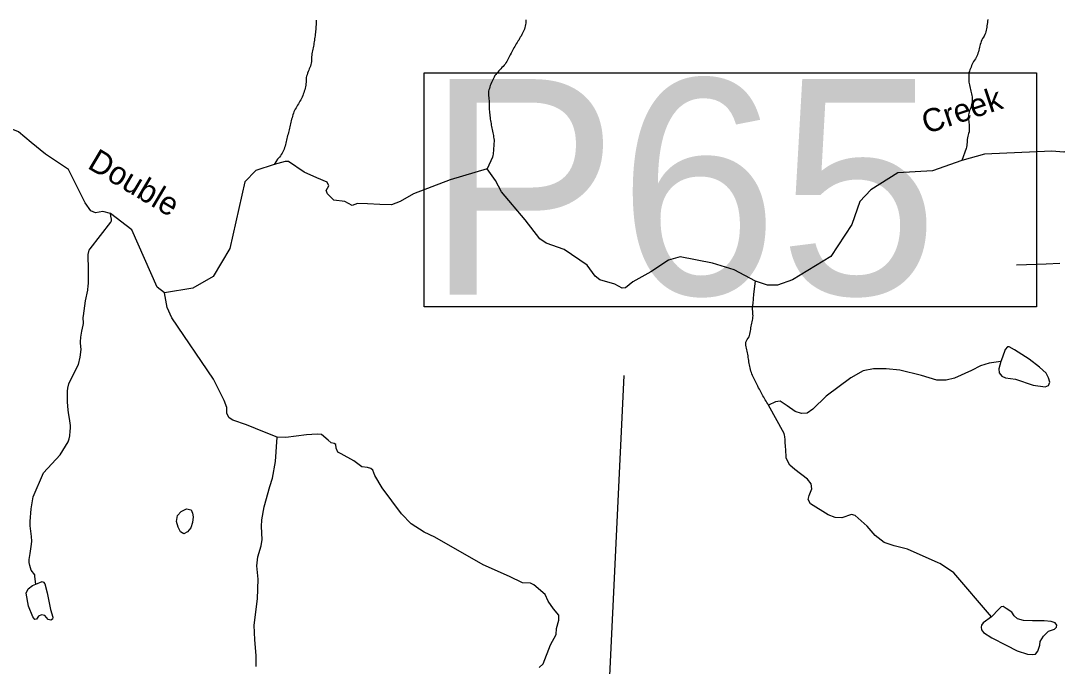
# Model space of a CAD drawing. Extents: x 1950930 to 2061844, y 904556 to 1017002.
# Drawn here: x 1972240 to 1978977, y 947382 to 951576 of the extents above; entities that cross this region are included whole.
import ezdxf

# ---------------------------------------------------------------- set-up
doc = ezdxf.new("R2010")
doc.units = 0
for name, color, linetype in [('Exist Hydrographic Creek Single Shore', 7, 'Continuous'), ('Exist Hydrographic Creek Single Shore Label', 7, 'Continuous'), ('Exist Hydrographic Misc Water Feature', 7, 'Continuous'), ('Exist Road Non-System Type 51', 7, 'Continuous'), ('Exist Road Secondary Structure Pipe Number Label', 7, 'Continuous')]:
    doc.layers.add(name, color=color, linetype=linetype)

msp = doc.modelspace()

# ---------------------------------------------------------------- linework, layer by layer
at = {"layer": 'Exist Hydrographic Creek Single Shore'}
for points in [[(1979490.9, 951341.5), (1979419.4, 951268.5), (1979383.6, 951162.2), (1979306.3, 951003.3), (1979273.4, 950893), (1979243.3, 950840), (1979200.4, 950804.2), (1979097.4, 950745.5), (1979020.1, 950721.2), (1978941.6, 950728.2), (1978504.9, 950709.7), (1978357.4, 950668.2)], [(1972823.1, 950324.4), (1972774.4, 950337.3), (1972725.8, 950327.2), (1972695.7, 950341.6), (1972658.5, 950393), (1972549.8, 950609.2), (1972400.9, 950709.7), (1972306.5, 950785.6), (1972224.9, 950854.4), (1972177.6, 950874.4), (1972146.2, 950870.1), (1971964.4, 950788.5)], [(1978357.4, 950668.2), (1978165.7, 950600.9), (1977941.5, 950588.1), (1977764.9, 950477.9), (1977694.8, 950400.6), (1977641.5, 950252.9), (1977504.5, 950045.1), (1977255.4, 949891.9), (1977158.1, 949859), (1977093.7, 949859), (1977015, 949884.6)], [(1973886.5, 950641.9), (1973767.7, 950601.8), (1973696.1, 950530.2), (1973599.5, 950096.8), (1973490.4, 949915.2), (1973357.6, 949839.3), (1973174.6, 949808.7)], [(1975271.8, 950613.8), (1975030, 950542.2), (1974792.4, 950452), (1974705.1, 950401.8), (1974650.7, 950378.9), (1974573.4, 950381.8), (1974494.7, 950386.1), (1974428.9, 950389), (1974394.5, 950376.1), (1974347.3, 950400.4), (1974274.3, 950410.4), (1974234.2, 950450.5), (1974224.2, 950472), (1974242.8, 950503.5), (1974231.4, 950527.9), (1974164.1, 950555.9), (1974081.1, 950591.7), (1973980.9, 950661.9), (1973959.4, 950660.5), (1973886.5, 950641.9)], [(1977015, 949884.6), (1976876.2, 949957.6), (1976735.9, 950000.6), (1976527, 950041.6), (1976451.1, 950020.1), (1976335.2, 949944.2), (1976217.8, 949879.7), (1976170.6, 949841.1), (1976149.1, 949838.2), (1976101.9, 949865.4), (1976003.2, 949892.6), (1975973.1, 949915.5), (1975921.6, 949987.1), (1975772.7, 950089.7), (1975654, 950129.8), (1975613.9, 950159.8), (1975518, 950281.6), (1975364.9, 950463.4), (1975324.8, 950537.9), (1975271.8, 950613.8)], [(1973174.6, 949808.7), (1973126.4, 949844.3), (1972961.9, 950218.4), (1972823.1, 950324.4)], [(1973906.1, 948870.4), (1973824.7, 948902.5), (1973706.6, 948949.6), (1973619.4, 948980.5), (1973594.2, 948995.4), (1973580.4, 949024.1), (1973579.3, 949063.1), (1973562.1, 949108.4), (1973519.7, 949195.6), (1973492.2, 949248), (1973221.6, 949645.6), (1973191.8, 949712.1), (1973174.6, 949808.7)], [(1975608.6, 947373.2), (1975636.2, 947397.5), (1975684.1, 947521.7), (1975720.7, 947589.1), (1975721.5, 947626.5), (1975737.7, 947680.9), (1975736.9, 947713.4), (1975703.6, 947755.4), (1975668.7, 947804.9), (1975649.2, 947847.2), (1975575.3, 947911.6), (1975553.4, 947921.4), (1975502.2, 947923.8), (1975416.1, 947965.2), (1975246.4, 948040.9), (1974931.6, 948221.5), (1974862.3, 948252.2), (1974777.9, 948307.5), (1974715.3, 948371.7), (1974589.5, 948541.9), (1974540.7, 948620.7), (1974528.5, 948655.6), (1974515.6, 948667.8), (1974494.4, 948674.3), (1974456.3, 948678.4), (1974404.3, 948716.6), (1974323.1, 948761.2), (1974301.2, 948773.4), (1974290.6, 948799.4), (1974288.2, 948822.1), (1974276, 948830.2), (1974258.1, 948834.3), (1974237.8, 948851.4), (1974194, 948887.1), (1974165.6, 948890.4), (1974096.5, 948886.3), (1973962.5, 948869.3), (1973906.1, 948870.4)]]:
    msp.add_lwpolyline(points, dxfattribs=at)
at = {"layer": 'Exist Hydrographic Misc Water Feature'}
for points in [[(1974159.4, 951578.7), (1974159.4, 951568.9), (1974159, 951559.1), (1974159, 951549.2), (1974158.6, 951538.5), (1974157.8, 951528.7), (1974157.2, 951518.9), (1974156.2, 951509), (1974154.9, 951499.3), (1974153.9, 951489.3), (1974152.7, 951478.8), (1974151.4, 951468.9), (1974149.8, 951459.1), (1974148.8, 951449.3), (1974146.9, 951439.5), (1974145.5, 951429.7), (1974144.3, 951419.8), (1974142.4, 951410.1), (1974140.8, 951400.2), (1974139.1, 951390.4), (1974136.9, 951380.6), (1974134.4, 951370.8), (1974132.8, 951361), (1974131.8, 951351.1), (1974130.5, 951340.6), (1974129.9, 951330.7), (1974129.5, 951320.9)], [(1975523.2, 951580.9), (1975522.8, 951570.2), (1975522, 951560.4), (1975521, 951550.5), (1975518.9, 951540.7), (1975516.5, 951531.8), (1975513.2, 951522), (1975509.5, 951512.2), (1975505.4, 951503.3), (1975501.3, 951494.4), (1975496.8, 951485.4), (1975491.7, 951476.5), (1975486.5, 951468.4), (1975481.4, 951459.5), (1975476.3, 951450.6), (1975471.4, 951442.5), (1975466, 951433.6), (1975460.7, 951425.5), (1975455.6, 951416.5), (1975450.4, 951408.4), (1975445.5, 951399.5), (1975440.4, 951390.6), (1975435.7, 951381.7), (1975430.8, 951373.6), (1975426.5, 951364.7), (1975421.9, 951354.8), (1975417.4, 951345.9), (1975412.9, 951337), (1975408.2, 951328.1), (1975403.7, 951320), (1975398.8, 951311), (1975393.6, 951302.1), (1975388.1, 951294)], [(1978526, 951583.6), (1978524.6, 951573.8), (1978523.4, 951564), (1978521.5, 951553.3), (1978520.3, 951543.6), (1978518.6, 951533.7), (1978517, 951523.9), (1978514.9, 951514.2), (1978512.9, 951504.3), (1978510, 951495.4), (1978506.7, 951485.5), (1978502.2, 951476.6), (1978496.9, 951468.5), (1978491.8, 951459.6), (1978486.9, 951450.7), (1978483, 951441.8), (1978479.7, 951432), (1978476.8, 951422.2), (1978473.9, 951413.3), (1978471.7, 951403.4), (1978469.4, 951393.6), (1978466.6, 951383.8), (1978464.3, 951374), (1978461.4, 951364.3), (1978458.6, 951354.5), (1978454.7, 951345.5), (1978450.6, 951336.6), (1978445.2, 951328.5), (1978439.5, 951319.6), (1978433.7, 951311.5), (1978428.6, 951302.6), (1978424.3, 951293.6), (1978420.4, 951284.7), (1978416.9, 951275), (1978413.4, 951265.9), (1978409.6, 951257), (1978405.7, 951247.3), (1978402.8, 951238.3), (1978401.8, 951228.5), (1978402.8, 951217.7), (1978402.6, 951207.9), (1978402.2, 951198.1), (1978402.4, 951188.2), (1978402.8, 951177.6)], [(1974129.5, 951320.9), (1974128.7, 951311), (1974127.2, 951301.2), (1974125.4, 951291.5), (1974123.1, 951281.6), (1974119.7, 951272.7), (1974115.4, 951263), (1974111.3, 951253.9), (1974107.4, 951245), (1974104.1, 951235.2), (1974100.8, 951225.4), (1974097.9, 951216.5), (1974095.9, 951206.7), (1974094.6, 951196.8), (1974094.4, 951186.3), (1974094.2, 951176.3), (1974093.8, 951166.5), (1974092.2, 951156.7), (1974090.3, 951146.9), (1974088.1, 951137.1), (1974085.4, 951127.3), (1974082.5, 951117.6), (1974079.7, 951107.7), (1974076.4, 951098.8), (1974072.9, 951089.1), (1974069, 951080.1), (1974064.5, 951071.1), (1974059.6, 951062.2), (1974054.7, 951054.1), (1974049.5, 951045.2), (1974044.4, 951036.3), (1974039.5, 951027.4), (1974034.2, 951019.3), (1974029, 951010.3), (1974023.9, 951002.2), (1974019.4, 950993.3), (1974015.5, 950983.6), (1974012, 950974.6), (1974008.9, 950964.8), (1974006.1, 950955.8), (1974003.2, 950946.1), (1974000.5, 950936.3), (1973997.7, 950926.5), (1973995.4, 950916.6), (1973993.1, 950906.9), (1973990.9, 950897), (1973989.2, 950887.3), (1973987.4, 950877.5), (1973985.1, 950867.6), (1973982.7, 950857.9), (1973980, 950848.9), (1973977.6, 950839.1), (1973974.7, 950829.4), (1973972, 950819.5), (1973969.6, 950809.7), (1973966.9, 950800), (1973964.4, 950790.9), (1973962.2, 950781.2), (1973959.9, 950771.4), (1973957.7, 950761.6), (1973954.8, 950751.8), (1973951.3, 950742), (1973947.4, 950733.1), (1973943.1, 950724.2), (1973938.4, 950715.2), (1973933.3, 950706.2), (1973927.9, 950698.3), (1973921.4, 950690), (1973914.8, 950682.9), (1973907.8, 950675.7), (1973886.5, 950641.9)], [(1975388.1, 951294), (1975381.8, 951286.9), (1975374.8, 951278.8), (1975367.8, 951271.5), (1975360.6, 951264.2), (1975354.3, 951257), (1975347.3, 951249.7), (1975340.1, 951242.5), (1975333.4, 951235.3), (1975327, 951227.2), (1975321.5, 951219.1), (1975316.8, 951210.2), (1975312.2, 951201.2), (1975307.9, 951192.3), (1975303.6, 951183.4), (1975299.5, 951174.4), (1975296, 951164.6), (1975292.1, 951154.9), (1975288.9, 951145.9), (1975286, 951136.1), (1975282.9, 951126.4), (1975280.9, 951117.4), (1975279.6, 951107.5), (1975279.6, 951097.7), (1975280.9, 951087), (1975281.9, 951077.2), (1975283.1, 951067.3), (1975283.7, 951057.4), (1975283.9, 951046.7), (1975284.1, 951036.9), (1975284.1, 951027.1), (1975284.8, 951017.2), (1975285.2, 951007.4), (1975285.4, 950997.5), (1975286.4, 950987.6), (1975287, 950977), (1975288.2, 950967.1), (1975289.3, 950957.2), (1975290.5, 950947.4), (1975292.1, 950937.4), (1975293.4, 950927.6), (1975295, 950917.8), (1975296.7, 950907.8), (1975298.5, 950898), (1975300.3, 950888), (1975302.4, 950878.2), (1975304.4, 950868.3), (1975306.5, 950858.4), (1975308.1, 950848.6), (1975310.2, 950839.5), (1975312.2, 950829.6), (1975313.7, 950819.6), (1975315.1, 950809.8), (1975316.1, 950800), (1975316.3, 950789.3), (1975315.9, 950779.5), (1975315.3, 950769.6), (1975314.5, 950759.8), (1975313.7, 950750), (1975312.7, 950739.3), (1975312, 950729.5), (1975311, 950719.7), (1975310, 950709.8), (1975308.8, 950700), (1975307.1, 950690.2), (1975271.8, 950613.8)], [(1978402.8, 951177.6), (1978404, 951167.7), (1978406.3, 951158.7), (1978408.7, 951148.7), (1978410.8, 951138.8), (1978413.4, 951129), (1978415.9, 951119), (1978418.6, 951110), (1978420.8, 951100), (1978422.5, 951090.2), (1978423.7, 951080.4), (1978424.3, 951070.4), (1978424.1, 951060.7), (1978423.3, 951050), (1978422.1, 951040.2), (1978420.4, 951030.3), (1978418, 951020.5), (1978414.9, 951010.7), (1978411.2, 951001.8), (1978407.7, 950992), (1978404.4, 950982.2), (1978402, 950973.3), (1978400.5, 950963.5), (1978399.9, 950953.6), (1978400.3, 950943.8), (1978400.9, 950933.1), (1978401.8, 950923.3), (1978402.8, 950913.3), (1978403.8, 950903.5), (1978404.8, 950893.7), (1978405.5, 950883), (1978405.5, 950873.2), (1978405, 950863.3), (1978403.6, 950853.5), (1978400.9, 950843.6), (1978398.1, 950833.9), (1978395.2, 950824.9), (1978393.4, 950814.3), (1978392.3, 950804.5), (1978391.7, 950794.6), (1978391.1, 950784.9), (1978390.3, 950774.9), (1978389.3, 950765.1), (1978387.4, 950755.4), (1978384.5, 950745.6), (1978357.4, 950668.2)], [(1972338.7, 947915), (1972332.4, 947965.3), (1972330.4, 947975.2), (1972306.8, 948006.8), (1972299, 948035.8), (1972295.3, 948055.4), (1972294.9, 948065.4), (1972295.1, 948075.9), (1972300, 948115.3), (1972310.3, 948175), (1972311.9, 948194.6), (1972310.3, 948224.2), (1972301.3, 948294.1), (1972300.6, 948304), (1972301.1, 948313.8), (1972301.3, 948323.6), (1972307.8, 948403.9), (1972320.1, 948482.5), (1972387.8, 948638.6), (1972495, 948756.1), (1972548.5, 948840.4), (1972554.7, 948860), (1972558.4, 948879.5), (1972561.5, 948909), (1972562.3, 948929.5), (1972562.3, 948939.4), (1972562.3, 948949.2), (1972561.9, 948959.9), (1972559.4, 948979.6), (1972549.8, 949028.3), (1972547.9, 949048.8), (1972544.7, 949098.1), (1972544.2, 949108.8), (1972543.6, 949138.3), (1972543.6, 949148.2), (1972544, 949168.7), (1972545.7, 949188.3), (1972552.4, 949217.7), (1972555.9, 949227.5), (1972615, 949341.9), (1972625.9, 949390.9), (1972633.6, 949440.1), (1972627.5, 949480.3), (1972627.5, 949490.2), (1972630.8, 949519.7), (1972637.7, 949558.9), (1972645.5, 949598.1), (1972646.8, 949608.8), (1972647.2, 949618.7), (1972646.2, 949638.3), (1972646.2, 949648.2), (1972646.8, 949658), (1972661.5, 949757), (1972675.1, 949825.7), (1972678.6, 949855.9), (1972679.4, 949865.7), (1972680.8, 949896.1), (1972680.8, 949905.9), (1972680.4, 949915.8), (1972680.6, 949925.6), (1972680, 949935.5), (1972680, 949945.4), (1972679.8, 949956), (1972679.4, 949965.9), (1972679.4, 949975.6), (1972679.4, 949985.6), (1972679.4, 949996.3), (1972678.6, 950016.8), (1972678.1, 950037.3), (1972678.3, 950047.1), (1972679, 950056.9), (1972682, 950075.7), (1972684.9, 950084.7), (1972690, 950093.7), (1972825.8, 950267.2), (1972829.1, 950276.2), (1972829.3, 950286.1), (1972825.4, 950306.6), (1972823.1, 950324.4)], [(1977100.3, 949078.6), (1977095.2, 949087), (1977089.8, 949095.3), (1977084.9, 949104.4), (1977079.6, 949112.7), (1977074.3, 949121), (1977069.1, 949130.1), (1977064.2, 949138.4), (1977059.5, 949147.5), (1977054.6, 949155.8), (1977050.1, 949165), (1977045.5, 949174.1), (1977040.8, 949182.4), (1977036.1, 949191.5), (1977031.6, 949200.7), (1977027.1, 949209.8), (1977022.8, 949218.1), (1977018.3, 949227.2), (1977013.8, 949236.3), (1977009.5, 949245.4), (1977004.9, 949254.5), (1977000.4, 949262.8), (1976996.3, 949272), (1976992.2, 949281.1), (1976989, 949291), (1976986.3, 949300), (1976984, 949309.9), (1976981.8, 949319.8), (1976979.5, 949329.7), (1976977.3, 949339.7), (1976975, 949349.5), (1976973.2, 949359.4), (1976971.5, 949369.3), (1976970.1, 949379.2), (1976968.7, 949389), (1976967, 949398.9), (1976965.8, 949408.8), (1976964.1, 949418.6), (1976962.5, 949428.6), (1976960.2, 949438.4), (1976957.6, 949448.4), (1976954.9, 949458.2), (1976953.1, 949468), (1976952.5, 949478), (1976953.3, 949487), (1976957, 949495.9), (1976962.3, 949504.8), (1976968, 949512.9), (1976973.8, 949521.9), (1976977.1, 949531.6), (1976979.7, 949540.6), (1976981.6, 949550.4), (1976983.2, 949560.2), (1976984.6, 949570.9), (1976986.1, 949580.6), (1976987.9, 949590.5), (1976989.6, 949600.3), (1976991.8, 949610.1), (1976994.1, 949619.9), (1976995.9, 949629.6), (1976997.6, 949639.5), (1976998.8, 949649.3), (1976999.8, 949659.1), (1976999.4, 949669), (1976998.8, 949679.7), (1976997.6, 949689.5), (1976997.2, 949699.4), (1976996.9, 949709.2), (1976997.6, 949719.1), (1976998.2, 949728.9), (1976999.8, 949739.5), (1977001, 949749.4), (1977002.1, 949759.1), (1977002.9, 949769.1), (1977003.3, 949778.9), (1977003.9, 949788.6), (1977004.5, 949799.3), (1977015, 949884.6)], [(1978610.8, 949362.1), (1978597.9, 949313.4), (1978599.3, 949289), (1978616.5, 949267.6), (1978640.8, 949256.1), (1978705.2, 949247.5), (1978821.1, 949208.8), (1978898.4, 949197.4), (1978919.9, 949206), (1978928.5, 949227.5), (1978921.3, 949256.1), (1978904.2, 949286.2), (1978861.2, 949324.8), (1978795.4, 949376.4), (1978699.5, 949438), (1978663.7, 949456.6), (1978653.7, 949456.6), (1978639.4, 949439.4), (1978620.8, 949389.3), (1978610.8, 949362.1)], [(1978610.8, 949362.1), (1978533.5, 949350.6), (1978477.7, 949334.9), (1978420.4, 949303.4), (1978310.2, 949253.2), (1978255.8, 949240.3), (1978194.3, 949241.8), (1978095.5, 949270.4), (1977953.9, 949304.8), (1977865.1, 949313.4), (1977782.1, 949313.4), (1977716.3, 949300.5), (1977636.1, 949256.1), (1977474.4, 949135.8), (1977388.5, 949051.3), (1977351.3, 949027), (1977314.1, 949024.1), (1977274, 949037), (1977221.1, 949074.2), (1977175.3, 949104.3), (1977145.2, 949100), (1977100.3, 949078.6)], [(1978549.2, 947702.2), (1978304.2, 947988.8), (1978296.2, 947994.7), (1978212.9, 948050.6), (1978203.7, 948054), (1978004.2, 948141.9), (1977916.6, 948163.6), (1977852.2, 948186.5), (1977793.6, 948230.9), (1977740.6, 948292.5), (1977663.3, 948362.5), (1977640.4, 948368.3), (1977577.5, 948346.8), (1977533.1, 948349.6), (1977488.7, 948366.8), (1977374.2, 948438.3), (1977358.5, 948465.5), (1977364.2, 948491.3), (1977381.4, 948535.7), (1977378.5, 948567.2), (1977354.2, 948597.2), (1977271.2, 948661.1), (1977238.3, 948688.3), (1977216.1, 948734.1), (1977215.9, 948743.9), (1977213.1, 948784.2), (1977211.4, 948813.7), (1977209.6, 948833.5), (1977208.6, 948854), (1977206.3, 948873.8), (1977204.7, 948883.6), (1977202.4, 948893.6), (1977100.3, 949078.6)], [(1973769.3, 947380.6), (1973769.3, 947451.3), (1973760.3, 947552.9), (1973757.1, 947648.9), (1973779, 947821.2), (1973783.1, 947948.8), (1973774.1, 948034.9), (1973780.6, 948093.4), (1973802.6, 948165), (1973809.9, 948206.5), (1973804.2, 948291), (1973807.4, 948332.4), (1973821.2, 948417.7), (1973858.6, 948551), (1973875.7, 948603.9), (1973896, 948711.9), (1973906.1, 948870.4)], [(1973347.6, 948398.9), (1973355.6, 948376.5), (1973359.9, 948352.7), (1973356, 948316.7), (1973344.6, 948280.8), (1973324.7, 948255), (1973300.9, 948242.3), (1973278.9, 948255.9), (1973262.3, 948285.7), (1973252.3, 948323.6), (1973258, 948360.6), (1973281.8, 948387.9), (1973317.7, 948404.3), (1973347.6, 948398.9)], [(1972338.7, 947915), (1972380, 947932.2), (1972388, 947928.7), (1972397.2, 947918.4), (1972412.1, 947858.8), (1972433.9, 947749.8), (1972447.6, 947700.4), (1972445.3, 947687.8), (1972435, 947682.1), (1972419, 947686.7), (1972396, 947710.8), (1972374.2, 947716.5), (1972354.8, 947708.5), (1972342.1, 947687.8), (1972331.8, 947686.7), (1972319.2, 947703.9), (1972290.6, 947772.7), (1972275.6, 947856.5), (1972287.1, 947885.2), (1972315.8, 947907), (1972338.7, 947915)], [(1978549.2, 947702.2), (1978496.3, 947663.6), (1978484.8, 947649.2), (1978482, 947636.4), (1978484.8, 947617.7), (1978497.7, 947600.6), (1978552.1, 947566.2), (1978645.1, 947518.9), (1978716.7, 947481.7), (1978783.9, 947460.2), (1978814, 947457.4), (1978835.5, 947461.7), (1978851.2, 947480.3), (1978864.1, 947518.9), (1978866.9, 947543.3), (1978887, 947577.6), (1978919.9, 947610.6), (1978958.5, 947622), (1978972.9, 947636.4), (1978974.3, 947649.2), (1978964.3, 947663.6), (1978937.1, 947673.6), (1978891.3, 947677.9), (1978815.4, 947677.9), (1978756.7, 947679.3), (1978719.5, 947689.3), (1978698.1, 947709.4), (1978680.9, 947733.7), (1978645.1, 947758.1), (1978625.1, 947771), (1978612.2, 947768.1), (1978596.5, 947753.8), (1978549.2, 947702.2)]]:
    msp.add_lwpolyline(points, dxfattribs=at)
at = {"layer": 'Exist Road Non-System Type 51'}
msp.add_lwpolyline([(1978993.4, 949999.2), (1978904, 949994.8), (1978713.1, 949987.3)], dxfattribs=at)
at = {"layer": 'Exist Road Secondary Structure Pipe Number Label'}
msp.add_line((1975951.8, 944850.2), (1976162.4, 949271.6), dxfattribs=at)
msp.add_lwpolyline([(1974861.2, 951236.8), (1978842.9, 951236.8), (1978842.9, 949717.4), (1974861.2, 949717.4)], close=True, dxfattribs=at)

# ---------------------------------------------------------------- texts
at = {"layer": 'Exist Hydrographic Creek Single Shore Label'}
for s, rotation, p in [('Creek', 18.44387, (1978126.3, 950838.7)), ('Creek', 18.44387, (1978126.3, 950838.7)), ('Creek', 18.44387, (1978126.3, 950838.7)), ('Double', 329.28727, (1972666.5, 950622))]:
    msp.add_text(s, height=150, rotation=rotation, dxfattribs=at).set_placement(p)
at = {"layer": 'Exist Road Secondary Structure Pipe Number Label'}
msp.add_text('P65', height=1400, dxfattribs=at).set_placement((1974874.3, 949796.5))

doc.saveas('drawing.dxf')
